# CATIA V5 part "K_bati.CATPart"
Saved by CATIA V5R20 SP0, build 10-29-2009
Part number: bati
Publications: "Hauteur_epaisseur_bati", "Largeur_epaisseur_bati"
Bounding box of the stored display mesh (mm): x -30 to 30, y -29.983 to 224.371, z 5.059 to 220
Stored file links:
  G:\Khaled_CFAO_2011\SIL\SIL_GR2\ahabrial\ahabrial\Khaled\CAD_ThinkMOTION\K_bati.CATPart
  G:\Données\Ecole\IFMA\2A\Thinkmotion2\Etape18\trotinette.CATProduct
  G:\Khaled_CFAO_2011\SIL\SIL_GR2\ahabrial\ahabrial\Khaled\CAD_ThinkMOTION\K_skl_arriere.CATPart
  G:\Khaled_CFAO_2011\SIL\SIL_GR2\ahabrial\ahabrial\Khaled\CAD_ThinkMOTION\K_arriere.CATPart
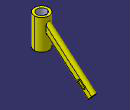
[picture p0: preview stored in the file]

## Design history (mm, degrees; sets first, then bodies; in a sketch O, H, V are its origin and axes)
Parameters
  Hauteur_epaisseur_bati = 20 mm
  Largeur_epaisseur_bati = 10 mm
  Diametre_bati = 60 mm
  Hauteur_bati2 = 100 mm
  Diametre_guidondsbati = 40 mm
External parameters (linked from other documents)
  External.hauteur_bati = 170 mm
  External.Longueur_bati = 200 mm
  External.epaisseur_arriere_trotinette = 30 mm
  External.Longueur_arriere_trotinette = 590 mm
  External.espace_frein = 50 mm
  External.Longueur_arriere = 500 mm
Set1
  Plane1 "Plan_bati": linked copy from another document
  Point1: linked copy from another document
  Plane2 "Plan_bati_guidon": linked copy from another document
  Point2: linked copy from another document
  Point3 "Point.3_arriere": linked copy from another document
Body1 (main body)
  Sketch1 on Plane2, origin (0, 0, 170), H (1, 0, 0), V (0, -1, 0)
    circle A1 centre (0, 0) radius 30
    point P1 (0, 0)
    reference projected point E1 (0, 0) from Point2
    radius A1 = 30 {= Diametre_bati /2}
    coincidence: P1 E1
  Pad1: profile Sketch1, direction (0, 0, 1), length 50 {= Hauteur_bati2 /2}, opposite side length 75 {= Hauteur_bati2 /(4/3)}
  Sketch2 on end face of Pad1, origin (0, 0, 220), H (-0.9906, -0.1369, 0), V (0.1369, -0.9906, 0)
    point P1 (0, 0)
  Hole1: placed by Sketch2, at (0, 0, 220) direction (0, 0, -1), diameter 40 {= Diametre_guidondsbati}, through (limit type 6)
  Point4 "Point_construction": (0, 200 {= External.Longueur_bati}, 30 {= External.epaisseur_arriere_trotinette})
  Plane3 "Plan_bati2": type OffsetPt, RefPlane Plane1, RefPoint Point4
  Sketch3 on Plane3, origin (0, 101.3062, -86.1103), H (-1, 0, 0), V (0, 0.6476, 0.7619)
    construction line L1 (0, 162.3879) -> (0, 142.3879)
    point P1 (0, 162.3879)
    line L2 (10, 162.3879) -> (10, 142.3879)
    line L3 (-10, 142.3879) -> (-10, 162.3879)
    arc A1 centre (0, 142.3879) radius 10 from (10, 142.3879) to (-10, 142.3879) cw
    arc A2 centre (0, 162.3879) radius 10 from (-10, 162.3879) to (10, 162.3879) cw
    reference projected point E1 (0, 152.3879) from Point4
    reference projected point E2 (0, 152.3879) from Point4
    distance L1 L2 = 10 {= Largeur_epaisseur_bati}
    length L1 = 20 {= Hauteur_epaisseur_bati}
    distance P1 E2 = 10 {= Hauteur_epaisseur_bati /2}
    vertical: L1 V
    tangency: A1 L2, A2 L2, A1 L3, A2 L3
    coincidence: L1 E1
  Pad2: profile Sketch3, direction (0, -0.7619, 0.6476), length 262.4881 {= sqrt((External.hauteur_bati *External.hauteur_bati )+(External.Longueur_bati *External.Longueur_bati ))}, opposite side length 15 {= External.epaisseur_arriere_trotinette /2}
  Sketch4 on face of Pad2 from Sketch3.L3, origin (10, 0, 0), H (0, 1, 0), V (0, 0, 1)
    construction line L1 (165.7571, 59.1064) -> (185.5562, 42.2772)
    line L2 (168.9954, 62.9161) -> (188.7944, 46.0869)
    line L3 (182.318, 38.4675) -> (162.5189, 55.2968)
    arc A1 centre (185.5562, 42.2772) radius 5 from (188.7944, 46.0869) to (182.318, 38.4675) cw
    arc A2 centre (165.7571, 59.1064) radius 5 from (162.5189, 55.2968) to (168.9954, 62.9161) cw
    reference projected line E1 (217.9056, 27.9047) -> (6.4765, 207.6194) from edge [face of Pad2 from Sketch3.A2 | face of Pad2 from Sketch3.L3]
    reference projected line E2 (217.9056, 27.9047) -> (6.4765, 207.6194) from edge [face of Pad2 from Sketch3.A2 | face of Pad2 from Sketch3.L3]
    distance L1 L2 = 5 {= Largeur_epaisseur_bati /2}
    distance L1 E2 = 10 {= Largeur_epaisseur_bati}
    tangency: A1 L2, A2 L2, A1 L3, A2 L3
    parallelism: E1 L1
  Pocket1: profile Sketch4, direction (-1, 0, 0), length 20 {= Largeur_epaisseur_bati *2}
